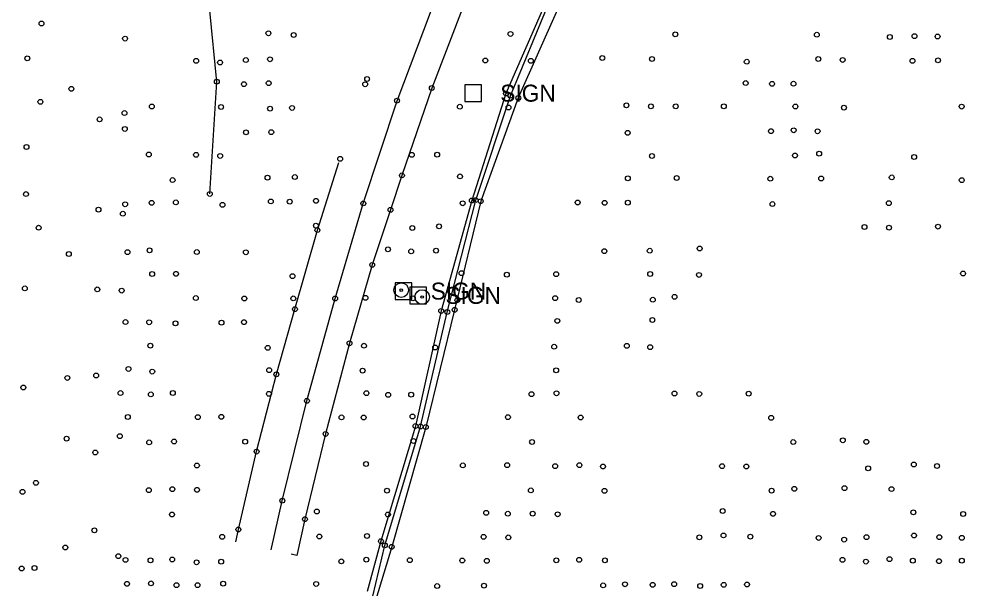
# Model space of a CAD drawing. Extents: x 20503438 to 20508873, y 7964251 to 7984667.
# Drawn here: x 20506683.1 to 20507078.6, y 7969482.5 to 7969717.3 of the extents above; entities that cross this region are included whole.
import ezdxf

# ---------------------------------------------------------------- set-up
doc = ezdxf.new("R2010")
doc.units = 0
for name, color, linetype in [('SurBreakLine', 7, 'Continuous'), ('SurConcreteSlab', 7, 'Continuous'), ('SurDrainageArrowDown', 7, 'Continuous'), ('SurEdgeRoadPaved', 7, 'Continuous'), ('SurRoadPoints', 7, 'Continuous'), ('SurSurveyPoints', 7, 'Continuous')]:
    doc.layers.add(name, color=color, linetype=linetype)

msp = doc.modelspace()

# ---------------------------------------------------------------- linework, layer by layer
at = {"layer": 'SurBreakLine'}
for points in [[(20507072.22, 7970031.81), (20507044.65, 7969983.45), (20507017.24, 7969942.09), (20506993.08, 7969899.77), (20506969.73, 7969857.18), (20506943.8, 7969809.14), (20506917.86, 7969765.01), (20506900.22, 7969724.24), (20506883.74, 7969686.63), (20506869.66, 7969642.53), (20506857.03, 7969597), (20506846.45, 7969549.54), (20506832.21, 7969502.12), (20506826.5, 7969481.38)], [(20507077.67, 7970029.62), (20507050.22, 7969980.63), (20507024.17, 7969937.47), (20506998.98, 7969896.23), (20506975.04, 7969854.03), (20506947.28, 7969804.04), (20506923.35, 7969761.61), (20506905.03, 7969721.23), (20506888.8, 7969684.78), (20506873.33, 7969642.22), (20506862.58, 7969597.47), (20506850.72, 7969549.13), (20506836.64, 7969499.73), (20506830.12, 7969478.04)]]:
    msp.add_lwpolyline(points, dxfattribs=at)
at = {"layer": 'SurConcreteSlab'}
for points in [[(20506786.98, 7969498.59), (20506791.56, 7969518.77), (20506801.71, 7969559.92), (20506813.33, 7969602.11), (20506824.94, 7969641.33), (20506838.85, 7969683.67), (20506855.36, 7969727.47), (20506871.04, 7969767.26), (20506887.39, 7969806.48), (20506907.03, 7969849.3), (20506926.87, 7969889.92), (20506946.4, 7969927.42), (20506964.13, 7969959.84), (20506998.31, 7970022.29), (20507028.85, 7970078.15), (20507050.93, 7970118.98), (20507063.43, 7970141.95), (20507094.89, 7970195.02), (20507112.55, 7970224.35), (20507146.84, 7970287.64), (20507180.2, 7970349.4), (20507227.5, 7970437.73), (20507263.67, 7970507.83), (20507275.78, 7970531.85)], [(20507015.79, 7970022.74), (20506988.66, 7969972.82), (20506974.4, 7969946.87), (20506957.8, 7969916.38), (20506943.98, 7969890.96), (20506942.58, 7969888.39), (20506939.78, 7969883.25), (20506912.31, 7969832.46), (20506905.2, 7969817.2), (20506894.52, 7969794.31), (20506880.24, 7969759.41), (20506853.16, 7969688.88), (20506840.87, 7969652.86), (20506836.17, 7969638.67), (20506828.63, 7969615.96), (20506819.26, 7969583.67), (20506809.41, 7969546.3), (20506800.9, 7969511.15), (20506797.61, 7969496.25), (20506795.23, 7969496.78)]]:
    msp.add_lwpolyline(points, dxfattribs=at)
at = {"layer": 'SurDrainageArrowDown'}
for points in [[(20506828.82, 7969479.38), (20506833.81, 7969500.36), (20506848.56, 7969549.36), (20506859.54, 7969596.56), (20506871.26, 7969642.69), (20506885.58, 7969685.72), (20506901.36, 7969723.92), (20506920.9, 7969764.04), (20506945.51, 7969806.46), (20506972.6, 7969855.74), (20506995.89, 7969898.43), (20507018.3, 7969939.97), (20507047.05, 7969981.99), (20507075.27, 7970030.65)], [(20506761.69, 7969645.23), (20506764.56, 7969691.5), (20506761.66, 7969720.78), (20506764.19, 7969744.34), (20506759.83, 7969777.16), (20506761.22, 7969804.86), (20506759.8, 7969808.78)]]:
    msp.add_lwpolyline(points, dxfattribs=at)
at = {"layer": 'SurEdgeRoadPaved'}
msp.add_lwpolyline([(20506772.35, 7969501.81), (20506773.47, 7969506.9), (20506780.98, 7969539.02), (20506789.14, 7969570.88), (20506796.77, 7969597.72), (20506806.03, 7969630.34), (20506814.9, 7969658.15)], dxfattribs=at)
at = {"layer": 'SurRoadPoints'}
for points in [[(20506870.19, 7969683.34), (20506870.19, 7969683.34), (20506873.62, 7969683.34), (20506873.62, 7969690.2), (20506866.76, 7969690.2), (20506866.76, 7969683.34), (20506870.19, 7969683.34)], [(20506841.52, 7969601.76), (20506841.52, 7969601.76), (20506844.95, 7969601.76), (20506844.95, 7969608.62), (20506838.09, 7969608.62), (20506838.09, 7969601.76), (20506841.52, 7969601.76)], [(20506847.58, 7969599.99), (20506847.58, 7969599.99), (20506851.01, 7969599.99), (20506851.01, 7969606.85), (20506844.15, 7969606.85), (20506844.15, 7969599.99), (20506847.58, 7969599.99)]]:
    msp.add_lwpolyline(points, dxfattribs=at)
for centre, radius in [((20506840.57, 7969605.57), 3), ((20506840.57, 7969605.57), 0.5), ((20506849.2, 7969602.73), 3), ((20506849.2, 7969602.73), 0.5)]:
    msp.add_circle(centre, radius, dxfattribs=at)
at = {"layer": 'SurSurveyPoints'}
for centre in [(20506692.31, 7969715.48), (20506785.84, 7969711.46), (20506796.24, 7969710.74), (20506885.6, 7969711.19), (20506953.53, 7969711.01), (20507011.82, 7969710.85), (20507041.94, 7969709.93), (20507052.09, 7969710.28), (20507061.61, 7969710.1), (20506726.78, 7969709.27), (20506686.48, 7969701.11), (20506756.06, 7969700.08), (20506765.92, 7969699.41), (20506776.53, 7969700.41), (20506786.52, 7969700.75), (20506875.22, 7969700.23), (20506894, 7969700.09), (20506923.43, 7969701.26), (20506943.93, 7969700.86), (20506982.96, 7969699.73), (20507012.45, 7969700.84), (20507022.49, 7969700.47), (20507051.25, 7969700.09), (20507061.76, 7969700.32), (20506764.56, 7969691.5), (20506775.75, 7969690.46), (20506785.97, 7969690.91), (20506825.72, 7969690.44), (20506826.51, 7969692.62), (20506982.53, 7969690.93), (20506993.4, 7969690.61), (20507002.21, 7969690.66), (20506704.65, 7969688.54), (20506853.16, 7969688.88), (20506883.74, 7969686.63), (20506691.89, 7969683.2), (20506838.85, 7969683.67), (20506885.58, 7969685.72), (20506888.8, 7969684.78), (20506726.56, 7969678.57), (20506737.78, 7969681.27), (20506766.34, 7969681.07), (20506786.53, 7969680.37), (20506795.6, 7969680.69), (20506864.7, 7969681.18), (20506884.77, 7969680.87), (20506933.38, 7969681.76), (20506943.47, 7969681.34), (20506953.7, 7969681.36), (20506973.54, 7969681.36), (20507003.02, 7969681.3), (20507023.01, 7969680.78), (20507071.53, 7969681.23), (20506716.28, 7969675.96), (20506726.69, 7969672.02), (20506776.6, 7969670.64), (20506787.02, 7969670.72), (20506933.89, 7969670.44), (20506992.94, 7969671.13), (20507002.3, 7969671.48), (20507012.16, 7969671.07), (20506686.18, 7969664.58), (20506736.58, 7969661.49), (20506756.04, 7969661.36), (20506765.96, 7969660.9), (20506815.4, 7969659.72), (20506844.94, 7969661.37), (20506855.36, 7969661.42), (20506943.89, 7969660.87), (20507002.84, 7969661.05), (20507012.78, 7969661.82), (20507051.96, 7969660.45), (20506746.36, 7969650.95), (20506785.45, 7969651.95), (20506796.74, 7969652.19), (20506840.87, 7969652.86), (20506864.79, 7969652.46), (20506933.96, 7969651.66), (20506954.08, 7969651.8), (20506992.68, 7969651.49), (20507013.61, 7969651.61), (20507042.72, 7969652.04), (20507071.56, 7969650.89), (20506685.95, 7969645.18), (20506761.69, 7969645.23), (20506871.26, 7969642.69), (20506715.81, 7969638.76), (20506726.81, 7969640.97), (20506737.71, 7969641.56), (20506747.72, 7969641.74), (20506766.9, 7969640.73), (20506786.83, 7969642.14), (20506794.64, 7969642.06), (20506805.44, 7969642.37), (20506824.94, 7969641.33), (20506836.17, 7969638.67), (20506865.9, 7969641.38), (20506869.66, 7969642.53), (20506873.33, 7969642.22), (20506913.3, 7969641.7), (20506924.39, 7969641.59), (20506933.96, 7969641.63), (20506993.54, 7969641.06), (20507041.53, 7969641.43), (20506725.83, 7969637.07), (20506691.16, 7969631.29), (20506805.43, 7969632.15), (20506845.14, 7969631.2), (20506856.17, 7969631.87), (20507031.5, 7969631.62), (20507041.58, 7969631.31), (20507061.79, 7969631.76), (20506806.03, 7969630.34), (20506703.57, 7969620.47), (20506727.77, 7969621.25), (20506736.87, 7969621.99), (20506756.34, 7969621.27), (20506776.56, 7969621.19), (20506835.09, 7969622.39), (20506844.66, 7969621.54), (20506854.93, 7969621.83), (20506924.28, 7969621.63), (20506942.99, 7969621.81), (20506963.57, 7969622.71), (20506828.63, 7969615.96), (20506737.94, 7969612.24), (20506747.77, 7969612.3), (20506795.75, 7969611.32), (20506865.41, 7969612.56), (20506884.08, 7969611.96), (20506904.41, 7969612.18), (20506943.14, 7969612.22), (20506963.3, 7969611.85), (20507072.11, 7969612.43), (20506685.45, 7969606.28), (20506715.33, 7969605.88), (20506725.37, 7969605.39), (20506755.91, 7969602.3), (20506775.91, 7969602.11), (20506796.11, 7969602.16), (20506813.33, 7969602.11), (20506825.88, 7969602.38), (20506845.38, 7969602.18), (20506863.73, 7969601.48), (20506904, 7969602.29), (20506913.73, 7969601.51), (20506944.27, 7969601.62), (20506953.22, 7969602.84), (20506796.77, 7969597.72), (20506857.03, 7969597), (20506859.54, 7969596.56), (20506862.58, 7969597.47), (20506726.93, 7969592.41), (20506736.69, 7969592.33), (20506747.53, 7969591.89), (20506766.51, 7969592.15), (20506775.79, 7969592.38), (20506904.89, 7969592.89), (20506944.08, 7969593.27), (20506819.26, 7969583.67), (20506737.19, 7969582.69), (20506785.57, 7969581.8), (20506825.24, 7969582.65), (20506854.55, 7969581.95), (20506903.58, 7969582.24), (20506933.56, 7969582.63), (20506943.17, 7969582.04), (20506728.17, 7969573.09), (20506737.98, 7969572), (20506786.17, 7969572.57), (20506824.66, 7969572.39), (20506904.44, 7969572.53), (20506703, 7969569.39), (20506714.85, 7969570.39), (20506789.14, 7969570.88), (20506684.85, 7969565.43), (20506724.89, 7969563.14), (20506737.37, 7969562.59), (20506746.47, 7969563.19), (20506786.06, 7969562.81), (20506801.71, 7969559.92), (20506826.22, 7969563.09), (20506835.22, 7969562.4), (20506844.7, 7969562.48), (20506894.26, 7969562.71), (20506904.57, 7969563.06), (20506953.17, 7969562.98), (20506963.39, 7969562.79), (20506983.76, 7969562.9), (20506727.9, 7969553.27), (20506756.74, 7969553.21), (20506766.46, 7969553.37), (20506815.95, 7969553.11), (20506825.11, 7969553.07), (20506845.24, 7969553.47), (20506884.55, 7969553.2), (20506914.5, 7969553.05), (20506993.02, 7969552.93), (20506846.45, 7969549.54), (20506848.56, 7969549.36), (20506850.72, 7969549.13), (20506702.67, 7969544.36), (20506724.59, 7969545.39), (20506809.41, 7969546.3), (20506736.69, 7969542.81), (20506746.97, 7969543.2), (20506776.29, 7969543.11), (20506845.6, 7969543.39), (20506894.49, 7969542.98), (20507002.13, 7969542.95), (20507022.57, 7969543.68), (20507032.23, 7969543.02), (20506714.49, 7969538.65), (20506780.98, 7969539.02), (20506756.39, 7969533.27), (20506826.09, 7969533.9), (20506865.99, 7969533.32), (20506884.26, 7969533.4), (20506904, 7969533.03), (20506914, 7969533.42), (20506923.72, 7969532.89), (20506972.8, 7969533.01), (20506982.78, 7969532.88), (20507032.99, 7969532.1), (20507051.84, 7969533.69), (20507061.35, 7969533.07), (20506690.03, 7969526.16), (20507023.25, 7969523.93), (20506684.49, 7969522.43), (20506736.54, 7969523.09), (20506746.24, 7969523.52), (20506756.4, 7969523.27), (20506834.73, 7969522.9), (20506893.98, 7969523.02), (20506924.34, 7969522.86), (20506993.21, 7969522.91), (20507002.59, 7969523.67), (20507042.64, 7969523.56), (20506791.56, 7969518.77), (20506746.13, 7969513.06), (20506805.78, 7969514.31), (20506835.1, 7969513.1), (20506875.57, 7969513.76), (20506884.48, 7969513.4), (20506894.76, 7969513.45), (20506905.03, 7969513.19), (20506973.06, 7969514.52), (20506993.77, 7969513.36), (20507051.63, 7969513.99), (20507072.14, 7969513.3), (20506800.9, 7969511.15), (20506714.14, 7969506.57), (20506773.47, 7969506.9), (20506826.46, 7969504.24), (20506973.41, 7969504.46), (20507051.91, 7969504.43), (20506766.8, 7969503.87), (20506806.85, 7969504), (20506832.21, 7969502.12), (20506833.81, 7969500.36), (20506874.52, 7969503.88), (20506884.71, 7969503.65), (20506963.43, 7969503.69), (20506984.45, 7969503.94), (20507012.58, 7969503.43), (20507023.11, 7969502.75), (20507032.29, 7969503.72), (20507062.32, 7969503.77), (20507071.58, 7969503.46), (20506702.16, 7969499.5), (20506836.64, 7969499.73), (20506723.99, 7969495.92), (20506726.96, 7969494.37), (20506737.24, 7969494.21), (20506746.21, 7969494.54), (20506756.24, 7969493.39), (20506766.39, 7969493.64), (20506815.91, 7969493.76), (20506826.19, 7969494.48), (20506844.12, 7969494.26), (20506865.73, 7969494.11), (20506875.86, 7969494), (20506904.49, 7969494.19), (20506913.9, 7969494.38), (20506924.51, 7969494.21), (20507022.44, 7969494.41), (20507032.08, 7969493.67), (20507041.81, 7969494.66), (20507051.4, 7969494.05), (20507062.2, 7969493.86), (20507071.58, 7969494.07), (20506684.14, 7969490.83), (20506689.46, 7969491.05), (20506727.58, 7969484.53), (20506737.45, 7969484.69), (20506767.19, 7969484.59), (20506805.55, 7969484.47), (20506747.94, 7969483.98), (20506756.65, 7969483.93), (20506855.41, 7969483.59), (20506874.69, 7969483.75), (20506923.79, 7969483.86), (20506932.81, 7969484.33), (20506944.21, 7969484.12), (20506953.04, 7969484.36), (20506963.74, 7969483.62), (20506973.48, 7969484.07), (20506983.09, 7969484.24)]:
    msp.add_circle(centre, 1, dxfattribs=at)

# ---------------------------------------------------------------- texts
at = {"layer": 'SurRoadPoints'}
for p in [(20506881.4, 7969683.27), (20506852.73, 7969601.69), (20506858.79, 7969599.92)]:
    msp.add_text('SIGN', height=6.995, rotation=360, dxfattribs=at).set_placement(p)

doc.saveas('drawing.dxf')
